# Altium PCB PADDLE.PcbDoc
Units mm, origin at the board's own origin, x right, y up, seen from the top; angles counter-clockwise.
Board outline 41.3 x 6.4 mm, 2 copper layers (Top Layer, Bottom Layer), stack 1.595 mm thick; 2 components, 3 nets, 10 pads, 3 vias.
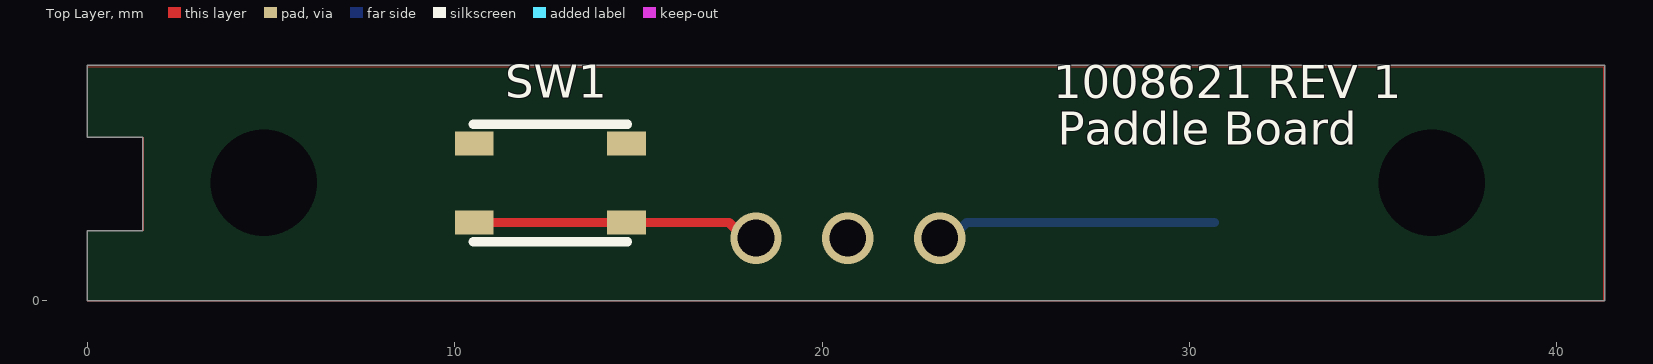
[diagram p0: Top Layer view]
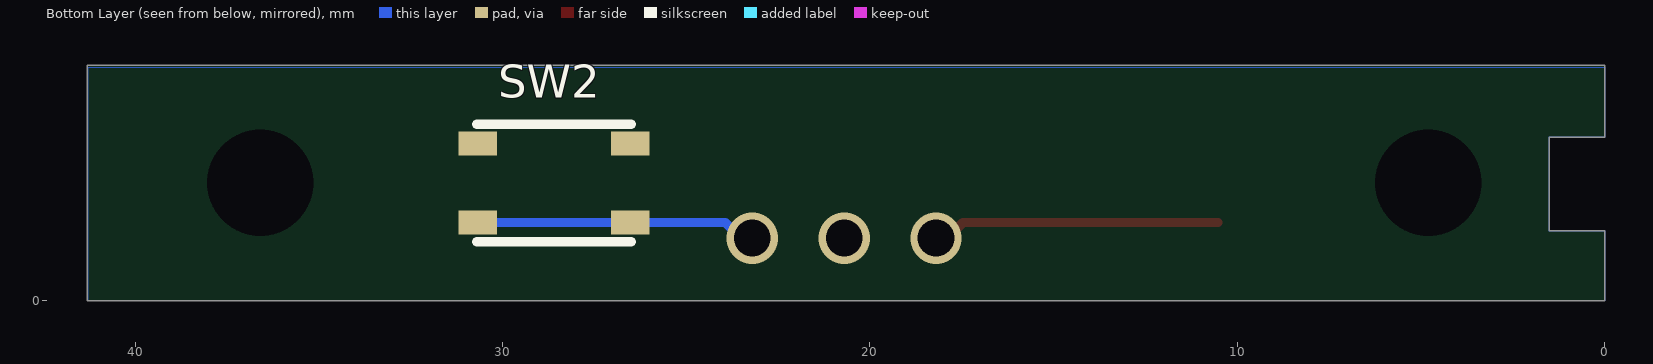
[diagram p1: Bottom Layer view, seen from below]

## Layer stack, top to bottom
Top Solder: solder mask 0.0152, Solder Resist, Dk 3.5
Top Layer: signal copper 0.0356
Dielectric 1: dielectric 1.524, FR-4, Dk 4.8
Bottom Layer: signal copper 0.0356
Bottom Solder: solder mask 0.0152, Solder Resist, Dk 3.5

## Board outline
0,1.9 1.5,1.9 1.5,4.445 0,4.445 0,6.4 41.3,6.4 41.3,0 0,0

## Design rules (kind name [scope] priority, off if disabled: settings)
AssemblyTestPointUsage [All] p0: scope1count=1 scope1_0_kind=Board scope1_0_value=Board scope2count=1 scope2_0_kind=Board scope2_0_value=Board commentlength=0
AssemblyTestpoint [All] p0: scope1count=1 scope1_0_kind=Board scope1_0_value=Board scope2count=1 scope2_0_kind=Board scope2_0_value=Board commentlength=0
Clearance [All] p0: scope1count=1 scope1_0_kind=Board scope1_0_value=Board scope2count=1 scope2_0_kind=Board scope2_0_value=Board commentlength=0 gap=0.254
Clearance [All] p1: gap=0.254 ignorepadtopadclearanceinfootprint=FALSE
ComponentClearance [All] p0: scope1count=1 scope1_0_kind=Board scope1_0_value=Board scope2count=1 scope2_0_kind=Board scope2_0_value=Board commentlength=0 gap=0.254 collisioncheckmode=3
DiffPairsRouting [All] p0: scope1count=1 scope1_0_kind=Board scope1_0_value=Board scope2count=1 scope2_0_kind=Board scope2_0_value=Board commentlength=0
FabricationTestPointUsage [All] p0: scope1count=1 scope1_0_kind=Board scope1_0_value=Board scope2count=1 scope2_0_kind=Board scope2_0_value=Board commentlength=0 valid=0 allowmultiple=FALSE
FabricationTestpoint [All] p0: scope1count=1 scope1_0_kind=Board scope1_0_value=Board scope2count=1 scope2_0_kind=Board scope2_0_value=Board commentlength=0 side=3 testpointundercomponent=TRUE minsize=1.016 maxsize=2.54 preferedsize=1.524 minholesize=0 maxholesize=1.016 preferedholesize=0.813 testpointgrid=0.025
FanoutControl Fanout_BGA [All] p0 off: scope1count=1 scope1_0_kind=Board scope1_0_value=Board scope2count=1 scope2_0_kind=Board scope2_0_value=Board commentlength=69 // Protel DXP Scope 1 Expression Was: IsBGA   Fanout_BGA (Default Rule)
FanoutControl Fanout_LCC [All] p0 off: scope1count=1 scope1_0_kind=Board scope1_0_value=Board scope2count=1 scope2_0_kind=Board scope2_0_value=Board commentlength=69 // Protel DXP Scope 1 Expression Was: IsLCC   Fanout_LCC (Default Rule)
FanoutControl Fanout_SOIC [All] p0 off: scope1count=1 scope1_0_kind=Board scope1_0_value=Board scope2count=1 scope2_0_kind=Board scope2_0_value=Board commentlength=71 // Protel DXP Scope 1 Expression Was: IsSOIC   Fanout_SOIC (Default Rule)
FanoutControl Fanout_Small [All] p0 off: scope1count=1 scope1_0_kind=Board scope1_0_value=Board scope2count=1 scope2_0_kind=Board scope2_0_value=Board commentlength=84 // Protel DXP Scope 1 Expression Was: (CompPinCount < 5)   Fanout_Small (Default Rule)
FanoutControl Fanout_Default [All] p0: scope1count=1 scope1_0_kind=Board scope1_0_value=Board scope2count=1 scope2_0_kind=Board scope2_0_value=Board commentlength=30 // Fanout_Default (Default Rule)
Height [All] p0: scope1count=1 scope1_0_kind=Board scope1_0_value=Board scope2count=1 scope2_0_kind=Board scope2_0_value=Board commentlength=0
HoleSize [All] p0: scope1count=1 scope1_0_kind=Board scope1_0_value=Board scope2count=1 scope2_0_kind=Board scope2_0_value=Board commentlength=0 absolutevalues=TRUE maxlimit=3 minlimit=0.025 maxpercent=80.000 minpercent=20.000
HoleSize [All] p1: absolutevalues=TRUE maxlimit=3 minlimit=0.025 maxpercent=80.000 minpercent=20.000
HoleToHoleClearance [All] p0: scope1count=1 scope1_0_kind=Board scope1_0_value=Board scope2count=1 scope2_0_kind=Board scope2_0_value=Board commentlength=0
LayerPairs [All] p0: scope1count=1 scope1_0_kind=Board scope1_0_value=Board scope2count=1 scope2_0_kind=Board scope2_0_value=Board commentlength=0 enforce=TRUE
MinimumSolderMaskSliver [All] p0: scope1count=1 scope1_0_kind=Board scope1_0_value=Board scope2count=1 scope2_0_kind=Board scope2_0_value=Board commentlength=0
NetAntennae [All] p0: scope1count=1 scope1_0_kind=Board scope1_0_value=Board scope2count=1 scope2_0_kind=Board scope2_0_value=Board commentlength=0
PasteMaskExpansion [All] p0: scope1count=1 scope1_0_kind=Board scope1_0_value=Board scope2count=1 scope2_0_kind=Board scope2_0_value=Board commentlength=0 expansion=0
PlaneClearance [All] p0: scope1count=1 scope1_0_kind=Board scope1_0_value=Board scope2count=1 scope2_0_kind=Board scope2_0_value=Board commentlength=0 clearance=0.508
PlaneConnect [All] p0: scope1count=1 scope1_0_kind=Board scope1_0_value=Board scope2count=1 scope2_0_kind=Board scope2_0_value=Board commentlength=0 planeconnectstyle=Relief reliefexpansion=0.508 reliefentries=4 reliefconductorwidth=0.254 reliefairgap=0.254
PolygonConnect [All] p0: scope1count=1 scope1_0_kind=Board scope1_0_value=Board scope2count=1 scope2_0_kind=Board scope2_0_value=Board commentlength=0 connectstyle=Relief reliefconductorwidth=0.254 reliefentries=4 polygonreliefangle="90 Angle"
PolygonConnect [All] p1: connectstyle=Relief reliefconductorwidth=0.254 reliefentries=4 polygonreliefangle="90 Angle" airgapwidth=0.254
RoutingCorners [All] p0: scope1count=1 scope1_0_kind=Board scope1_0_value=Board scope2count=1 scope2_0_kind=Board scope2_0_value=Board commentlength=0 cornerstyle=45-Degree minsetback=2.54 maxsetback=2.54
RoutingLayers [All] p0: scope1count=1 scope1_0_kind=Board scope1_0_value=Board scope2count=1 scope2_0_kind=Board scope2_0_value=Board commentlength=0 top layer=Automatic bottom layer=Automatic
RoutingPriority [All] p0: scope1count=1 scope1_0_kind=Board scope1_0_value=Board scope2count=1 scope2_0_kind=Board scope2_0_value=Board commentlength=0
RoutingTopology [All] p0: scope1count=1 scope1_0_kind=Board scope1_0_value=Board scope2count=1 scope2_0_kind=Board scope2_0_value=Board commentlength=0 topology=Shortest
RoutingVias [All] p0: scope1count=1 scope1_0_kind=Board scope1_0_value=Board scope2count=1 scope2_0_kind=Board scope2_0_value=Board commentlength=0 holewidth=0.711 width=1.27 viastyle="Through Hole" minholewidth=0.711 minwidth=1.27 maxholewidth=0.711 maxwidth=1.27
RoutingVias [All] p1: holewidth=0.711 width=1.27 viastyle="Through Hole" minholewidth=0.711 minwidth=1.27 maxholewidth=0.711 maxwidth=1.27
ShortCircuit [All] p0: scope1count=1 scope1_0_kind=Board scope1_0_value=Board scope2count=1 scope2_0_kind=Board scope2_0_value=Board commentlength=0 allowed=FALSE
SilkToBoardRegionClearance [All] p0: scope1count=1 scope1_0_kind=Board scope1_0_value=Board scope2count=1 scope2_0_kind=Board scope2_0_value=Board commentlength=0
SilkToSilkClearance [All] p0: scope1count=1 scope1_0_kind=Board scope1_0_value=Board scope2count=1 scope2_0_kind=Board scope2_0_value=Board commentlength=0
SilkToSolderMaskClearance [All] p0 off: scope1count=1 scope1_0_kind=Board scope1_0_value=Board scope2count=1 scope2_0_kind=Board scope2_0_value=Board commentlength=44 // Protel DXP Scope 1 Expression Was: IsPad
SilkToSolderMaskClearance [IsPad] p1: minsilkscreentomaskgap=0.05 clearancetoexposedcopper=TRUE
SolderMaskExpansion [All] p0: scope1count=1 scope1_0_kind=Board scope1_0_value=Board scope2count=1 scope2_0_kind=Board scope2_0_value=Board commentlength=0 expansion=0.102
SolderMaskExpansion [All] p1: expansion=0.102 istentingtop=FALSE
SupplyNets "Schematic Supply Nets" [All] p0: scope1count=1 scope1_0_kind=Net scope1_0_value=GND scope2count=1 scope2_0_kind=Board scope2_0_value=Board commentlength=0 voltage=0.000
SupplyNets "Schematic Supply Nets" [InNet('GND')] p1: voltage=0.000
UnRoutedNet [All] p0: scope1count=1 scope1_0_kind=Board scope1_0_value=Board scope2count=1 scope2_0_kind=Board scope2_0_value=Board commentlength=0
UnpouredPolygon [All] p0: scope1count=1 scope1_0_kind=Board scope1_0_value=Board scope2count=1 scope2_0_kind=Board scope2_0_value=Board commentlength=0
Width [All] p0: scope1count=1 scope1_0_kind=Board scope1_0_value=Board scope2count=1 scope2_0_kind=Board scope2_0_value=Board commentlength=0 maxlimit=0.254 minlimit=0.254 preferedwidth=0.254
Width [All] p1: maxlimit=0.254 minlimit=0.254 preferedwidth=0.254
28 further rules are at their usual default settings.

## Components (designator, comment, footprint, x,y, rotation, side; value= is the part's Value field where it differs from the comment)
SW1 "327381" SW-PCB-4P-4.2MM-3.2MM-SMT 12.6,3.2 r0 top
SW2 "" SW-PCB-4P-4.2MM-3.2MM-SMT 28.6,3.2 r180 bottom

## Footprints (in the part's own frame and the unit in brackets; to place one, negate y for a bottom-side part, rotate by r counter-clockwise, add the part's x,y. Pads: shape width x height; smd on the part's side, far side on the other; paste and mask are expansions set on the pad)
SW-PCB-4P-4.2MM-3.2MM-SMT [mm]
  rect 1.05x0.65 smd: 1(-2.075,1.075) 2(2.075,1.075) 3(-2.075,-1.075) 4(2.075,-1.075)
  silkscreen extent -2.1,-1.6 2.1,1.6

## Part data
SW1 SW2: library part CMP-024-000065-1, "Switch, PTS810 SJM 250 SMTR LFS, SMT, SPST, momentary on, push-button, C&K: PTS810 SJM 250 SMTR LFS"

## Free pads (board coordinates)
  round 0 hole 2.9: 3(4.8,3.2) 3(36.6,3.2)

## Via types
v1: diameter 1.4, hole 1, Top Layer to Bottom Layer, 3 vias

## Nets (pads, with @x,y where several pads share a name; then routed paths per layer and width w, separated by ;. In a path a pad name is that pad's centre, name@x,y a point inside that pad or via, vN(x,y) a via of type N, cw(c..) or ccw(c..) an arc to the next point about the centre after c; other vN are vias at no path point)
GND: SW1.1 SW1.2 SW2.1 SW2.2
  other v1: 20.7,1.7
NetSW1_3: SW1.3 SW1.4 | length 7.9
  Top Layer w0.254: SW1.3 SW1.4 17.465,2.125 17.89,1.7 v1(18.2,1.7)
NetSW2_3: SW2.3 SW2.4 | length 7.7
  Bottom Layer w0.254: v1(23.2,1.7) 23.51,1.7 23.935,2.125 SW2.4 SW2.3

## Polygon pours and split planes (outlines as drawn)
GND on Bottom Layer "GND_L02_P000" (solid, pour order 0): 41.275,6.35 0,6.35 0,4.445 1.524,4.445 1.524,1.905 0,1.905 0,0 41.275,0
GND on Top Layer "GND_L01_P001" (solid, pour order 1): 41.275,6.35 0,6.35 0,4.445 1.524,4.445 1.524,1.905 0,1.905 0,0 41.275,0

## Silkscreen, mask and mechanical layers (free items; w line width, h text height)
Top Overlay:
  text "1008621 REV 1" at 26.289,5.207 h1.52
  text "Paddle Board" at 26.416,3.937 h1.52
Mechanical 1:
  circle w0.254: c4.8,3.2 r1.45
  circle w0.254: c36.6,3.2 r1.45
  lines w0.254: 0,0 0,1.9 1.5,1.9 1.5,4.445 0,4.445 0,6.4 41.3,6.4 41.3,0 0,0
